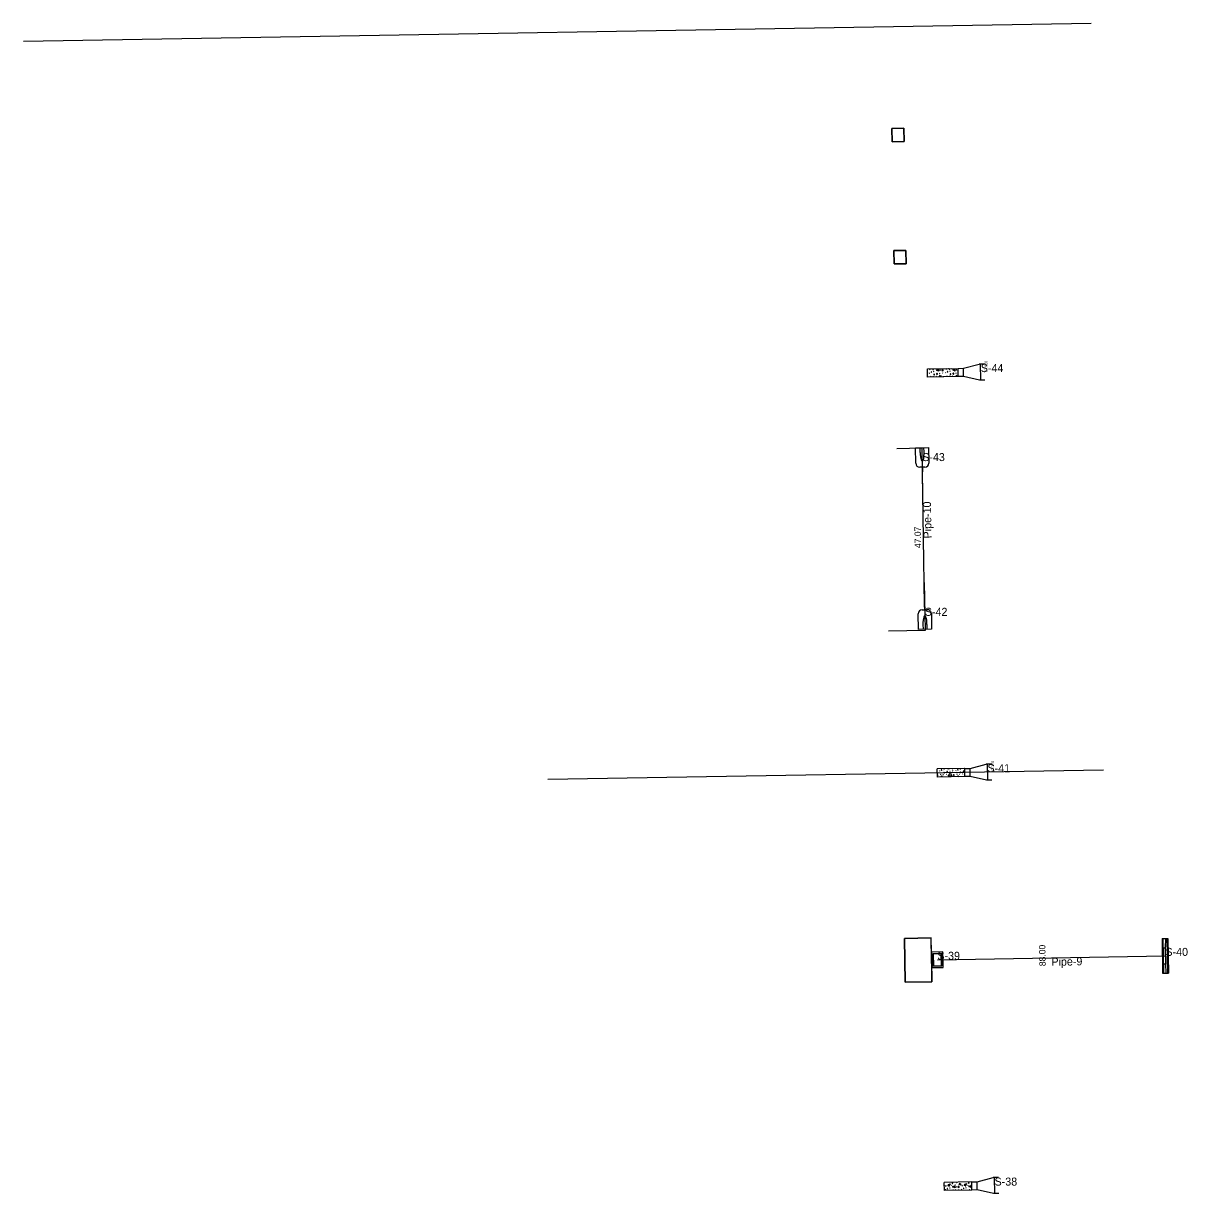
# Model space of a CAD drawing. Extents: x 925371 to 925937, y 853654 to 858024.
# Drawn here: x 925399.5 to 925835.9, y 856450.1 to 856888.8 of the extents above; entities that cross this region are included whole.
import ezdxf

# ---------------------------------------------------------------- set-up
doc = ezdxf.new("R2010")
doc.units = 0
for name, color, linetype in [('DitchPavt', 7, 'Continuous'), ('Endwall', 7, 'Continuous'), ('GPKDrBack_dp', 7, 'Continuous'), ('GPKDrBottom_dp', 7, 'Continuous'), ('GPKDrCellIns_dp', 7, 'Continuous'), ('GPKDrFront_dp', 7, 'Continuous'), ('GPKDrPipe_dp', 7, 'Continuous'), ('InletClosedFlume', 7, 'Continuous'), ('InletDBI', 7, 'Continuous'), ('MES', 7, 'Continuous'), ('Miscellaneous5', 7, 'Continuous'), ('Miscellaneous6', 7, 'Continuous'), ('NonPlottingEle_dp', 7, 'Continuous'), ('PipeCulvert', 7, 'Continuous'), ('PipeCulvertSS', 7, 'Continuous'), ('Scratch1_dp', 7, 'Continuous')]:
    doc.layers.add(name, color=color, linetype=linetype)

msp = doc.modelspace()

# ---------------------------------------------------------------- linework, layer by layer
at = {"layer": 'DitchPavt'}
for p, q in [((925729.51, 856849.49), (925725.01, 856849.42)), ((925729.6, 856844.5), (925729.51, 856849.49)), ((925739.03, 856757.72), (925739.17, 856757.81)), ((925739.1, 856758.92), (925739.26, 856759.02)), ((925739.29, 856759.19), (925739.42, 856759.27)), ((925740.13, 856759.27), (925740.15, 856759.28)), ((925740.56, 856758.88), (925740.35, 856758.97)), ((925740.51, 856759.08), (925740.4, 856759.29)), ((925740.58, 856759.29), (925740.51, 856759.08)), ((925740.87, 856758.22), (925740.65, 856758.31)), ((925741.37, 856759.22), (925741.46, 856759.3)), ((925742.91, 856757.59), (925743.06, 856757.71)), ((925744.16, 856757.68), (925743.95, 856757.77)), ((925745.16, 856757.82), (925745.29, 856757.92)), ((925745.23, 856759.02), (925745.38, 856759.12)), ((925745.41, 856759.29), (925745.54, 856759.37)), ((925746.25, 856759.37), (925746.27, 856759.39)), ((925746.68, 856758.99), (925746.48, 856759.08)), ((925746.63, 856759.19), (925746.52, 856759.39)), ((925746.71, 856759.39), (925746.63, 856759.19)), ((925746.99, 856758.32), (925746.77, 856758.41)), ((925747.49, 856759.33), (925747.59, 856759.41)), ((925749.03, 856757.7), (925749.19, 856757.81)), ((925749.85, 856756.4), (925749.8, 856759.45)), ((925739.71, 856756.34), (925739.49, 856756.43)), ((925740.58, 856756.25), (925740.37, 856756.33)), ((925741.58, 856756.48), (925741.71, 856756.57)), ((925745.83, 856756.44), (925745.61, 856756.53)), ((925746.7, 856756.35), (925746.49, 856756.44)), ((925747.71, 856756.58), (925747.83, 856756.68)), ((925742.83, 856608.52), (925742.97, 856608.62)), ((925744.66, 856609.02), (925744.44, 856609.11)), ((925746.33, 856609.17), (925745.97, 856609.35)), ((925746.31, 856609.36), (925746.33, 856609.17)), ((925747.95, 856608.48), (925747.75, 856608.57)), ((925748.95, 856608.63), (925749.09, 856608.72)), ((925750.79, 856609.13), (925750.57, 856609.22)), ((925752.33, 856609.34), (925752.1, 856609.45)), ((925743.51, 856607.14), (925743.29, 856607.23)), ((925744.38, 856607.05), (925744.16, 856607.14)), ((925745.38, 856607.28), (925745.5, 856607.38)), ((925746.7, 856608.4), (925746.86, 856608.51)), ((925749.63, 856607.25), (925749.41, 856607.34)), ((925750.51, 856607.15), (925750.29, 856607.24)), ((925751.5, 856607.39), (925751.63, 856607.48)), ((925739.74, 856545.96), (925729.74, 856545.79)), ((925739.88, 856537.72), (925739.74, 856545.96)), ((925739.83, 856540.63), (925739.74, 856545.96)), ((925739.88, 856537.72), (925740.02, 856529.47)), ((925740.02, 856529.47), (925739.93, 856534.8)), ((925744.71, 856451.26), (925744.66, 856454.31)), ((925744.67, 856453.25), (925744.71, 856453.13)), ((925744.71, 856453.13), (925744.68, 856453.15)), ((925755.02, 856451.44), (925744.71, 856451.26)), ((925745.04, 856451.58), (925745.18, 856451.67)), ((925745.11, 856452.78), (925745.26, 856452.88)), ((925745.29, 856453.05), (925745.45, 856453.14)), ((925746.56, 856452.74), (925746.36, 856452.83)), ((925746.87, 856452.08), (925746.65, 856452.17)), ((925747.37, 856453.08), (925747.52, 856453.21)), ((925748.63, 856453.32), (925748.79, 856453.42)), ((925748.91, 856451.45), (925749.07, 856451.57)), ((925750.16, 856451.54), (925749.96, 856451.63)), ((925751.16, 856451.68), (925751.3, 856451.78)), ((925751.23, 856452.88), (925751.39, 856452.98)), ((925751.42, 856453.15), (925751.57, 856453.25)), ((925752.69, 856452.85), (925752.48, 856452.94)), ((925753, 856452.18), (925752.78, 856452.27)), ((925753.49, 856453.19), (925753.65, 856453.32)), ((925754.76, 856453.43), (925754.91, 856453.52))]:
    msp.add_line(p, q, dxfattribs=at)
for points in [[(925725.01, 856849.42), (925725.1, 856844.42), (925729.6, 856844.5)], [(925730.38, 856798.67), (925730.29, 856803.67), (925725.79, 856803.59), (925725.88, 856798.59), (925730.38, 856798.67)], [(925749.85, 856756.4), (925738.35, 856756.21), (925738.3, 856759.25), (925749.8, 856759.45)], [(925739.76, 856757.95), (925739.87, 856758.01), (925739.88, 856758.1), (925739.84, 856758.17), (925739.8, 856758.17), (925739.71, 856758.13), (925739.67, 856758.07), (925739.71, 856758.01), (925739.76, 856757.95)], [(925740.03, 856759.28), (925740.04, 856759.26), (925740.13, 856759.27)], [(925742.54, 856758.37), (925741.67, 856758.79), (925742.46, 856759.12), (925742.54, 856758.37)], [(925743.12, 856758.66), (925743.17, 856758.79), (925743.11, 856758.78), (925743.03, 856758.75), (925743.06, 856758.67), (925743.12, 856758.66)], [(925743.81, 856758.61), (925744.08, 856758.55), (925744.17, 856758.66), (925744.17, 856758.74), (925744.17, 856758.91), (925743.98, 856758.99), (925743.81, 856758.94), (925743.76, 856758.83), (925743.76, 856758.7), (925743.81, 856758.61)], [(925745.89, 856758.05), (925745.99, 856758.11), (925746.01, 856758.21), (925745.96, 856758.27), (925745.93, 856758.27), (925745.84, 856758.24), (925745.79, 856758.17), (925745.84, 856758.11), (925745.89, 856758.05)], [(925746.15, 856759.38), (925746.16, 856759.37), (925746.25, 856759.37)], [(925748.66, 856758.47), (925747.79, 856758.9), (925748.58, 856759.22), (925748.66, 856758.47)], [(925749.25, 856758.76), (925749.29, 856758.89), (925749.23, 856758.89), (925749.15, 856758.86), (925749.19, 856758.78), (925749.25, 856758.76)], [(925740.76, 856757.03), (925740.87, 856757), (925740.95, 856757.09), (925740.93, 856757.18), (925740.85, 856757.28), (925740.77, 856757.24), (925740.73, 856757.21), (925740.7, 856757.15), (925740.7, 856757.12), (925740.76, 856757.03)], [(925741.84, 856757.25), (925741.98, 856757.2), (925742.1, 856757.24), (925742.12, 856757.35), (925742.1, 856757.42), (925742, 856757.52), (925741.86, 856757.51), (925741.79, 856757.42), (925741.79, 856757.34), (925741.84, 856757.25)], [(925742.68, 856756.28), (925743.23, 856756.85), (925743.5, 856756.3)], [(925744.46, 856756.31), (925744.45, 856756.34), (925744.37, 856756.34), (925744.28, 856756.31)], [(925746.89, 856757.13), (925747, 856757.1), (925747.07, 856757.2), (925747.05, 856757.29), (925746.98, 856757.38), (925746.9, 856757.35), (925746.85, 856757.32), (925746.82, 856757.25), (925746.82, 856757.22), (925746.89, 856757.13)], [(925747.96, 856757.35), (925748.1, 856757.31), (925748.23, 856757.34), (925748.24, 856757.45), (925748.22, 856757.53), (925748.13, 856757.62), (925747.99, 856757.62), (925747.91, 856757.52), (925747.91, 856757.44), (925747.96, 856757.35)], [(925748.8, 856756.39), (925749.36, 856756.95), (925749.62, 856756.4)], [(925752.33, 856609.46), (925742.03, 856609.28)], [(925752.38, 856606.42), (925742.08, 856606.24), (925742.03, 856609.28)], [(925743.56, 856608.75), (925743.67, 856608.82), (925743.68, 856608.91), (925743.63, 856608.97), (925743.6, 856608.97), (925743.51, 856608.94), (925743.46, 856608.88), (925743.51, 856608.81), (925743.56, 856608.75)], [(925747.77, 856609.38), (925747.88, 856609.36), (925747.9, 856609.38)], [(925749.68, 856608.86), (925749.79, 856608.92), (925749.8, 856609.01), (925749.76, 856609.08), (925749.73, 856609.08), (925749.63, 856609.04), (925749.59, 856608.98), (925749.63, 856608.92), (925749.68, 856608.86)], [(925742.07, 856606.78), (925742.09, 856606.77), (925742.2, 856606.85), (925742.17, 856606.96), (925742.12, 856607.04), (925742.07, 856607.04)], [(925743.89, 856606.27), (925743.91, 856606.32), (925743.8, 856606.54), (925743.64, 856606.53), (925743.52, 856606.45), (925743.5, 856606.38), (925743.53, 856606.27)], [(925744.56, 856607.83), (925744.67, 856607.8), (925744.74, 856607.9), (925744.73, 856607.99), (925744.65, 856608.08), (925744.57, 856608.05), (925744.52, 856608.02), (925744.49, 856607.96), (925744.49, 856607.92), (925744.56, 856607.83)], [(925745.63, 856608.05), (925745.77, 856608.01), (925745.9, 856608.04), (925745.91, 856608.15), (925745.9, 856608.23), (925745.8, 856608.32), (925745.66, 856608.32), (925745.58, 856608.22), (925745.58, 856608.15), (925745.63, 856608.05)], [(925747.53, 856606.6), (925746.15, 856606.76), (925747.03, 856607.65), (925747.53, 856606.6)], [(925748.11, 856606.91), (925748.22, 856606.88), (925748.32, 856606.96), (925748.29, 856607.07), (925748.24, 856607.14), (925748.16, 856607.14), (925748.06, 856607.11), (925748.01, 856607.02), (925748.06, 856606.92), (925748.11, 856606.91)], [(925750.02, 856606.38), (925750.04, 856606.42), (925749.92, 856606.64), (925749.77, 856606.64), (925749.64, 856606.56), (925749.63, 856606.48), (925749.65, 856606.37)], [(925750.68, 856607.94), (925750.79, 856607.91), (925750.87, 856608), (925750.85, 856608.09), (925750.77, 856608.19), (925750.69, 856608.15), (925750.65, 856608.12), (925750.62, 856608.06), (925750.62, 856608.03), (925750.68, 856607.94)], [(925751.76, 856608.16), (925751.9, 856608.11), (925752.02, 856608.15), (925752.04, 856608.26), (925752.02, 856608.33), (925751.92, 856608.43), (925751.78, 856608.42), (925751.71, 856608.33), (925751.71, 856608.25), (925751.76, 856608.16)], [(925752.37, 856606.86), (925752.28, 856606.87), (925752.37, 856606.96)], [(925740.02, 856529.47), (925730.02, 856529.3), (925729.74, 856545.79), (925739.74, 856545.96)], [(925729.74, 856545.79), (925730.02, 856529.3), (925740.02, 856529.47)], [(925739.93, 856534.8), (925739.88, 856537.72), (925739.83, 856540.63)], [(925754.96, 856454.48), (925744.66, 856454.31)], [(925745.77, 856451.81), (925745.87, 856451.87), (925745.89, 856451.96), (925745.84, 856452.03), (925745.81, 856452.03), (925745.72, 856451.99), (925745.67, 856451.93), (925745.72, 856451.87), (925745.77, 856451.81)], [(925746.13, 856453.13), (925746.2, 856453.17), (925746.23, 856453.25), (925746.19, 856453.31), (925746.13, 856453.33), (925746.05, 856453.31), (925745.98, 856453.28), (925746.01, 856453.19), (925746.04, 856453.12), (925746.13, 856453.13)], [(925746.51, 856452.94), (925746.22, 856453.47), (925746.8, 856453.73), (925746.51, 856452.94)], [(925747.75, 856453.9), (925747.78, 856453.93), (925747.81, 856454.03), (925747.76, 856454.12), (925747.71, 856454.15), (925747.62, 856454.12), (925747.59, 856453.99), (925747.62, 856453.93), (925747.68, 856453.9), (925747.75, 856453.9)], [(925748.54, 856452.23), (925747.67, 856452.65), (925748.47, 856452.98), (925748.54, 856452.23)], [(925748.07, 856451.32), (925748.01, 856451.38), (925747.87, 856451.37), (925747.82, 856451.32)], [(925749.13, 856452.52), (925749.17, 856452.65), (925749.11, 856452.64), (925749.03, 856452.61), (925749.07, 856452.53), (925749.13, 856452.52)], [(925749.23, 856454.38), (925749.24, 856454.37), (925749.26, 856454.3), (925749.33, 856454.27), (925749.3, 856454.27)], [(925749.33, 856454.27), (925749.43, 856454.37), (925749.43, 856454.39)], [(925749.82, 856452.47), (925750.09, 856452.41), (925750.18, 856452.52), (925750.18, 856452.6), (925750.17, 856452.77), (925749.98, 856452.85), (925749.81, 856452.8), (925749.77, 856452.69), (925749.77, 856452.56), (925749.82, 856452.47)], [(925750.84, 856453.24), (925750.22, 856453.54), (925750.57, 856454.01), (925750.84, 856453.24)], [(925751.89, 856451.91), (925752, 856451.97), (925752.01, 856452.07), (925751.97, 856452.13), (925751.93, 856452.13), (925751.84, 856452.1), (925751.79, 856452.03), (925751.84, 856451.97), (925751.89, 856451.91)], [(925752.26, 856453.23), (925752.32, 856453.28), (925752.35, 856453.36), (925752.32, 856453.42), (925752.26, 856453.43), (925752.18, 856453.42), (925752.1, 856453.38), (925752.13, 856453.29), (925752.17, 856453.23), (925752.26, 856453.23)], [(925752.64, 856453.05), (925752.35, 856453.57), (925752.92, 856453.83), (925752.64, 856453.05)], [(925753.87, 856454.01), (925753.9, 856454.04), (925753.93, 856454.13), (925753.88, 856454.23), (925753.84, 856454.26), (925753.74, 856454.22), (925753.71, 856454.1), (925753.75, 856454.04), (925753.81, 856454.01), (925753.87, 856454.01)], [(925754.67, 856452.33), (925753.8, 856452.76), (925754.59, 856453.08), (925754.67, 856452.33)], [(925754.19, 856451.43), (925754.13, 856451.48), (925753.99, 856451.48), (925753.95, 856451.42)]]:
    msp.add_lwpolyline(points, dxfattribs=at)
at = {"layer": 'Endwall'}
for p, q in [((925826.26, 856545.68), (925828.42, 856545.72)), ((925826.26, 856545.68), (925826.48, 856532.69)), ((925826.59, 856545.69), (925826.81, 856532.69)), ((925827.53, 856545.71), (925827.48, 856542.21)), ((925828.09, 856545.72), (925828.31, 856532.72)), ((925828.42, 856545.72), (925828.65, 856532.72)), ((925826.65, 856542.19), (925827.48, 856542.21)), ((925827.48, 856542.21), (925827.59, 856536.21)), ((925826.75, 856536.19), (925827.59, 856536.21)), ((925827.59, 856536.21), (925827.75, 856532.71)), ((925826.48, 856532.69), (925828.65, 856532.72))]:
    msp.add_line(p, q, dxfattribs=at)
at = {"layer": 'GPKDrBack_dp'}
for p, q in [((925751.83, 856757.96), (925751.83, 856757.96)), ((925736.3, 856729.73), (925736.3, 856729.73)), ((925737.44, 856661.66), (925737.44, 856661.66)), ((925754.36, 856607.97), (925754.36, 856607.97)), ((925826.7, 856539.19), (925826.7, 856539.19)), ((925742.1, 856534.84), (925742.1, 856534.84)), ((925744.21, 856537.79), (925744.21, 856537.79)), ((925756.99, 856452.99), (925756.99, 856452.99))]:
    msp.add_line(p, q, dxfattribs=at)
at = {"layer": 'GPKDrBottom_dp'}
for p, q in [((925758.33, 856758.07), (925758.33, 856758.07)), ((925736.38, 856724.7), (925736.38, 856724.7)), ((925737.35, 856666.69), (925737.35, 856666.69)), ((925760.85, 856608.08), (925760.85, 856608.08)), ((925740.51, 856539.98), (925740.51, 856539.98)), ((925742.01, 856540), (925742.01, 856540)), ((925743.51, 856540.03), (925743.51, 856540.03)), ((925827.54, 856539.21), (925827.54, 856539.21)), ((925740.55, 856537.73), (925740.55, 856537.73)), ((925740.59, 856535.48), (925740.59, 856535.48)), ((925742.05, 856537.75), (925742.05, 856537.75)), ((925742.09, 856535.5), (925742.09, 856535.5)), ((925743.55, 856537.78), (925743.55, 856537.78)), ((925743.59, 856535.53), (925743.59, 856535.53)), ((925763.49, 856453.1), (925763.49, 856453.1))]:
    msp.add_line(p, q, dxfattribs=at)
at = {"layer": 'GPKDrCellIns_dp'}
for p, q in [((925758.33, 856758.07), (925758.33, 856758.07)), ((925736.38, 856724.7), (925736.38, 856724.7)), ((925737.35, 856666.69), (925737.35, 856666.69)), ((925760.85, 856608.08), (925760.85, 856608.08)), ((925827.54, 856539.21), (925827.54, 856539.21)), ((925742.05, 856537.75), (925742.05, 856537.75)), ((925763.49, 856453.1), (925763.49, 856453.1))]:
    msp.add_line(p, q, dxfattribs=at)
at = {"layer": 'GPKDrFront_dp'}
for p, q in [((925759.83, 856758.09), (925759.83, 856758.09)), ((925736.42, 856722.41), (925736.42, 856722.41)), ((925737.32, 856668.98), (925737.32, 856668.98)), ((925762.35, 856608.11), (925762.35, 856608.11)), ((925742, 856540.67), (925742, 856540.67)), ((925827.54, 856539.21), (925827.54, 856539.21)), ((925739.88, 856537.72), (925739.88, 856537.72)), ((925764.99, 856453.13), (925764.99, 856453.13))]:
    msp.add_line(p, q, dxfattribs=at)
at = {"layer": 'GPKDrPipe_dp'}
for p, q in [((925736.45, 856720.73), (925736.45, 856720.73)), ((925737.29, 856670.66), (925737.29, 856670.66)), ((925742.01, 856540), (925742.01, 856540)), ((925827.2, 856539.2), (925827.2, 856539.2)), ((925740.55, 856537.73), (925740.55, 856537.73)), ((925742.09, 856535.5), (925742.09, 856535.5)), ((925743.55, 856537.78), (925743.55, 856537.78))]:
    msp.add_line(p, q, dxfattribs=at)
at = {"layer": 'InletClosedFlume'}
for p, q in [((925751.8, 856759.48), (925757.78, 856761.06)), ((925751.85, 856756.44), (925751.8, 856759.48)), ((925759.78, 856761.09), (925757.78, 856761.06)), ((925758.38, 856755.07), (925758.28, 856761.07)), ((925757.88, 856755.06), (925751.85, 856756.44)), ((925759.88, 856755.09), (925757.88, 856755.06)), ((925754.33, 856609.49), (925760.3, 856611.07)), ((925754.38, 856606.45), (925754.33, 856609.49)), ((925762.3, 856611.11), (925760.3, 856611.07)), ((925760.91, 856605.08), (925760.8, 856611.08)), ((925760.41, 856605.07), (925754.38, 856606.45)), ((925762.41, 856605.11), (925760.41, 856605.07)), ((925756.96, 856454.51), (925762.94, 856456.1)), ((925764.94, 856456.13), (925762.94, 856456.1)), ((925763.54, 856450.1), (925763.44, 856456.1)), ((925757.02, 856451.47), (925756.96, 856454.51)), ((925763.04, 856450.1), (925757.02, 856451.47)), ((925765.04, 856450.13), (925763.04, 856450.1))]:
    msp.add_line(p, q, dxfattribs=at)
for points in [[(925751.85, 856756.44), (925749.85, 856756.4), (925749.8, 856759.45), (925751.8, 856759.48)], [(925754.38, 856606.45), (925752.38, 856606.42), (925752.33, 856609.46), (925754.33, 856609.49)], [(925757.02, 856451.47), (925755.02, 856451.44), (925754.96, 856454.48), (925756.96, 856454.51)]]:
    msp.add_lwpolyline(points, dxfattribs=at)
at = {"layer": 'InletDBI'}
for p, q in [((925744.16, 856540.71), (925739.83, 856540.63)), ((925739.83, 856540.63), (925739.93, 856534.8)), ((925743.7, 856540.03), (925740.32, 856539.97)), ((925740.32, 856539.97), (925740.4, 856535.47)), ((925740.51, 856539.98), (925740.59, 856535.48)), ((925743.59, 856535.53), (925743.51, 856540.03)), ((925743.77, 856535.53), (925743.7, 856540.03)), ((925744.26, 856534.87), (925744.16, 856540.71)), ((925739.93, 856534.8), (925744.26, 856534.87)), ((925740.4, 856535.47), (925743.77, 856535.53))]:
    msp.add_line(p, q, dxfattribs=at)
at = {"layer": 'MES'}
for p, q in [((925733.84, 856729.68), (925738.76, 856729.77)), ((925733.94, 856723.87), (925733.84, 856729.68)), ((925735.58, 856727.97), (925735.59, 856729.71)), ((925737.07, 856727.99), (925737, 856729.74)), ((925738.76, 856729.77), (925738.85, 856723.95)), ((925737.38, 856722.42), (925735.46, 856722.39)), ((925736.42, 856722.41), (925736.45, 856720.73)), ((925737.32, 856668.98), (925737.29, 856670.66)), ((925734.98, 856661.62), (925734.88, 856667.44)), ((925736.36, 856668.96), (925738.28, 856669)), ((925739.8, 856667.52), (925739.9, 856661.7)), ((925739.9, 856661.7), (925734.98, 856661.62)), ((925736.66, 856663.39), (925736.74, 856661.65)), ((925738.16, 856663.42), (925738.15, 856661.67))]:
    msp.add_line(p, q, dxfattribs=at)
for centre, start, end in [((925735.43, 856723.89), 180.9573, 270.9573), ((925737.35, 856723.92), 270.9573, 0.9573), ((925736.38, 856667.46), 90.9741, 180.9741), ((925738.3, 856667.5), 0.9741, 90.9741)]:
    msp.add_arc(centre, 1.5, start, end, dxfattribs=at)
for centre, major_axis in [((925736.33, 856727.7), (0.05, -3)), ((925737.41, 856663.69), (-0.05, 3))]:
    msp.add_ellipse(centre, major_axis=major_axis, ratio=0.25, start_param=4.617261, end_param=7.949056, dxfattribs=at)
at = {"layer": 'Miscellaneous5'}
msp.add_line((925799.65, 856888.78), (925399.46, 856881.98), dxfattribs=at)
at = {"layer": 'Miscellaneous6'}
msp.add_line((925804.35, 856608.82), (925596.06, 856605.28), dxfattribs=at)
at = {"layer": 'NonPlottingEle_dp'}
for points in [[(925736.6, 856711.52), (925736.3, 856729.51), (925726.83, 856729.35)], [(925737.14, 856679.22), (925737.45, 856661.22), (925723.68, 856660.98)]]:
    msp.add_lwpolyline(points, dxfattribs=at)
at = {"layer": 'PipeCulvert'}
msp.add_line((925737.29, 856670.66), (925736.45, 856720.73), dxfattribs=at)
at = {"layer": 'PipeCulvertSS'}
msp.add_line((925742.05, 856537.75), (925827.54, 856539.21), dxfattribs=at)
at = {"layer": 'Scratch1_dp'}
msp.add_line((925725.01, 856849.42), (925729.51, 856849.49), dxfattribs=at)
for points in [[(925725.1, 856844.42), (925725.01, 856849.42), (925729.51, 856849.49), (925729.6, 856844.5)], [(925725.88, 856798.59), (925725.79, 856803.59), (925730.29, 856803.67), (925730.38, 856798.67)]]:
    msp.add_lwpolyline(points, close=True, dxfattribs=at)

# ---------------------------------------------------------------- texts
at = {"layer": 'NonPlottingEle_dp'}
for s, height, rotation, p in [('17.620', 1, 90.9573, (925760.83, 856758.09)), ('17.620', 1, 90.9573, (925760.83, 856758.09)), ('17.620', 1, 90.9573, (925760.83, 856758.09)), ('17.620', 1, 90.9573, (925760.83, 856758.09)), ('Pipe-10', 3, 90.9603, (925739.87, 856695.74)), ('47.07', 2.4, 90.9741, (925735.99, 856692.11)), ('17.170', 1, 90.9741, (925763.36, 856608.13)), ('88.00', 2.4, 90.9741, (925782.66, 856535.37)), ('Pipe-9', 3, 0.9741, (925784.84, 856535.48))]:
    msp.add_text(s, height=height, rotation=rotation, dxfattribs=at).set_placement(p)
for s, p in [('S-44', (925758.33, 856758.07)), ('S-43', (925736.38, 856724.7)), ('S-42', (925737.35, 856666.69)), ('S-41', (925760.85, 856608.08)), ('S-39', (925742.05, 856537.75)), ('S-40', (925827.54, 856539.21)), ('S-38', (925763.49, 856453.1))]:
    msp.add_text(s, height=3, dxfattribs=at).set_placement(p)

doc.saveas('drawing.dxf')
